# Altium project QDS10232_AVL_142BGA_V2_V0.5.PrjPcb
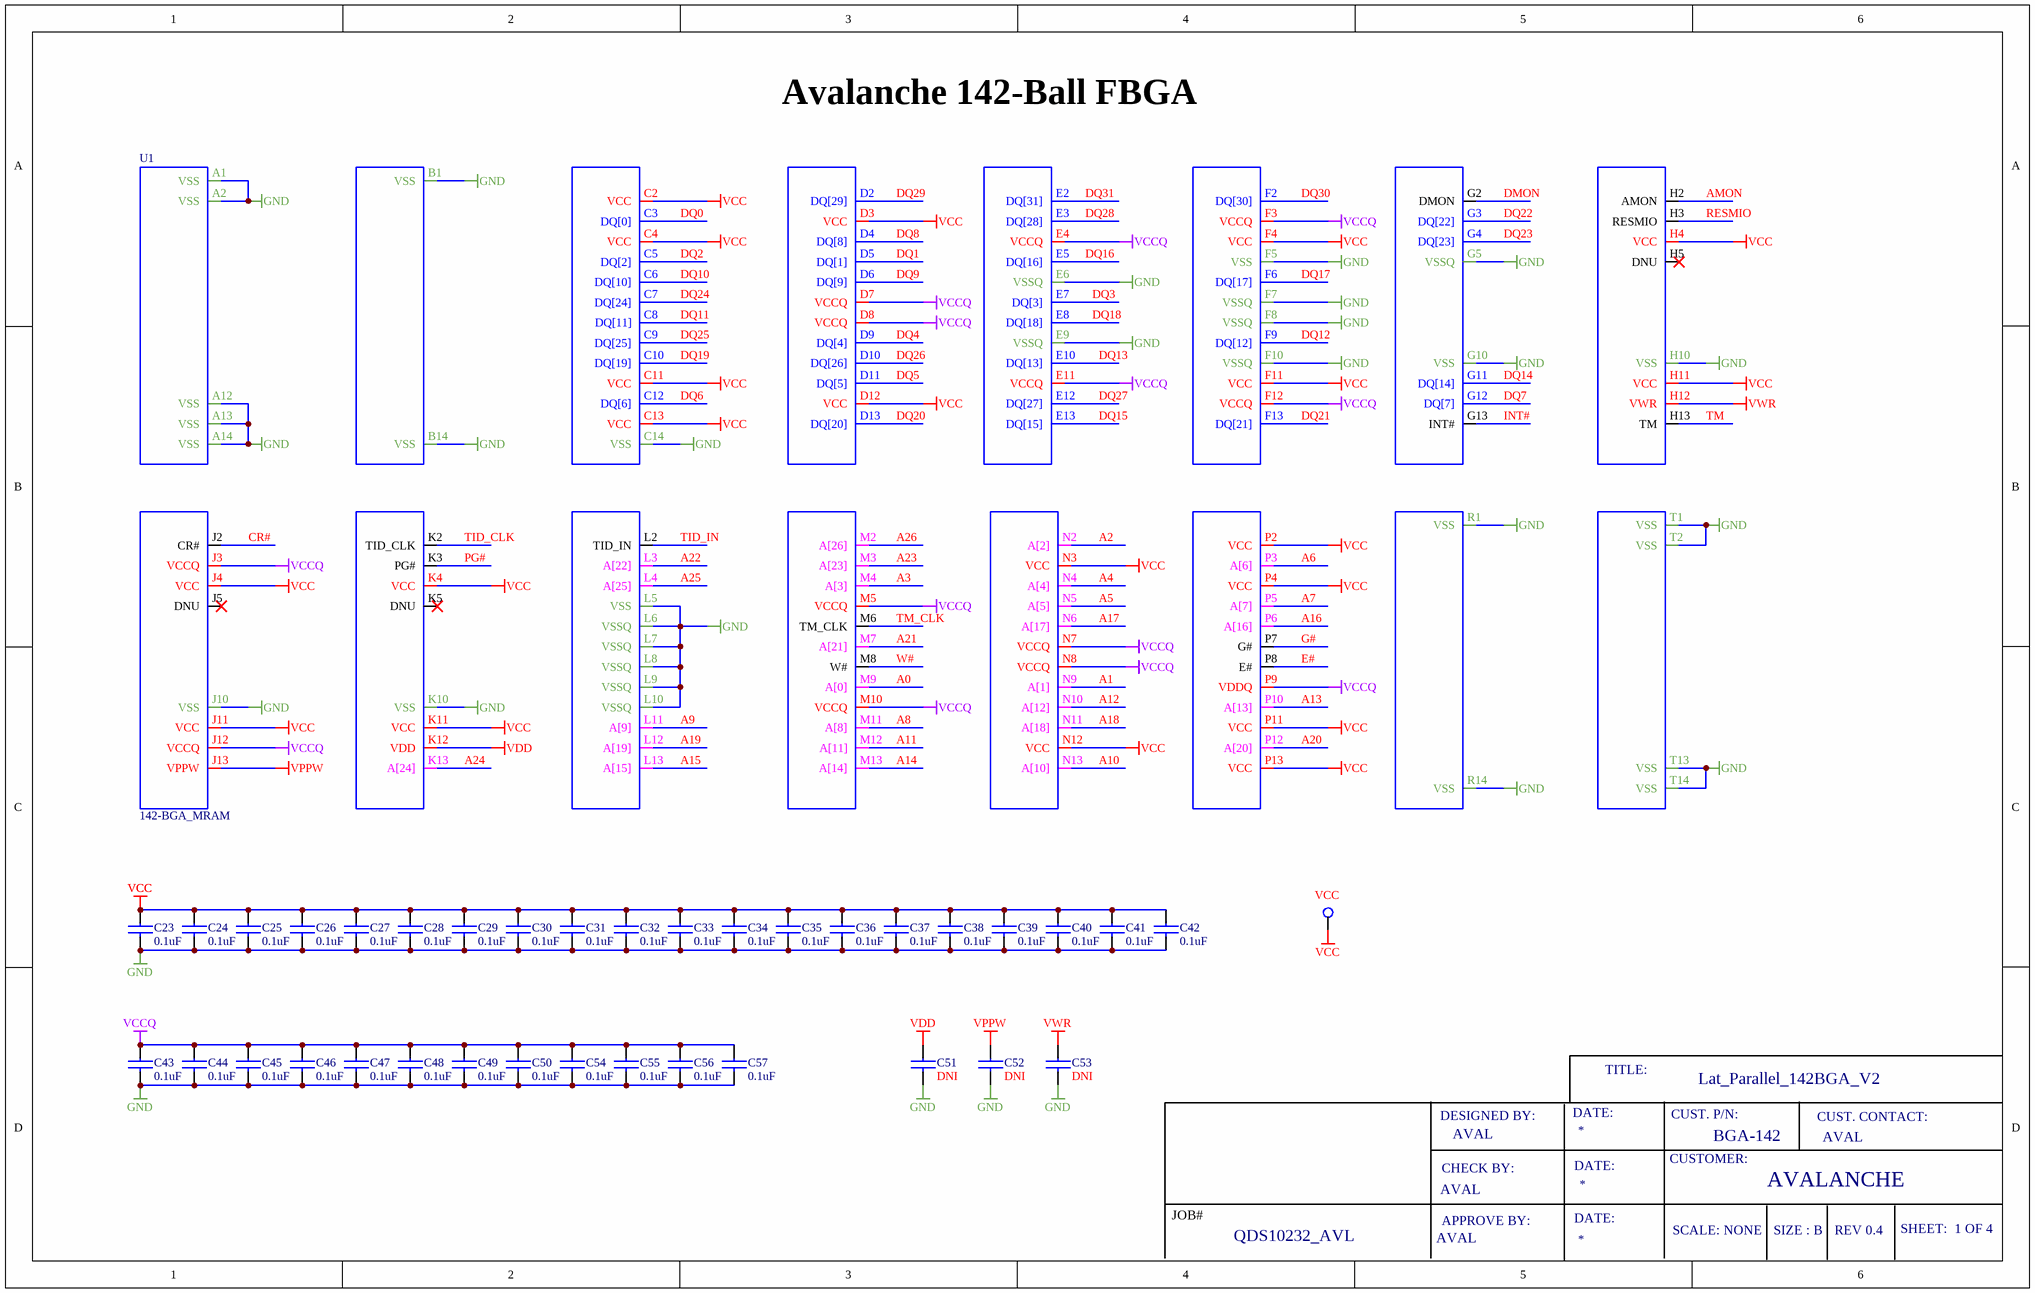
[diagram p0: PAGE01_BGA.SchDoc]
4 sheets, 249 parts. Net scope: global (net labels, ports and power ports of the same name join across sheets).
Board file: QDS10232_AVL_V0.5.PcbDoc
Sheets:
  PAGE01_BGA.SchDoc
  PAGE02_CIRCUIT.SchDoc
  PAGE03_USB_REG.SchDoc
  PAGE04_CON_J3-J4-J6-J8.SchDoc

## Sheet PAGE01_BGA.SchDoc
size B

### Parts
C23  0.1uF  [N_0402]
C24  0.1uF  [N_0402]
C25  0.1uF  [N_0402]
C26  0.1uF  [N_0402]
C27  0.1uF  [N_0402]
C28  0.1uF  [N_0402]
C29  0.1uF  [N_0402]
C30  0.1uF  [N_0402]
C31  0.1uF  [N_0402]
C32  0.1uF  [N_0402]
C33  0.1uF  [N_0402]
C34  0.1uF  [N_0402]
C35  0.1uF  [N_0402]
C36  0.1uF  [N_0402]
C37  0.1uF  [N_0402]
C38  0.1uF  [N_0402]
C39  0.1uF  [N_0402]
C40  0.1uF  [N_0402]
C41  0.1uF  [N_0402]
C42  0.1uF  [N_0402]
C43  0.1uF  [N_0402]
C44  0.1uF  [N_0402]
C45  0.1uF  [N_0402]
C46  0.1uF  [N_0402]
C47  0.1uF  [N_0402]
C48  0.1uF  [N_0402]
C49  0.1uF  [N_0402]
C50  0.1uF  [N_0402]
C51  DNI  [N_0402]
C52  DNI  [N_0402]
C53  DNI  [N_0402]
C54  0.1uF  [N_0402]
C55  0.1uF  [N_0402]
C56  0.1uF  [N_0402]
C57  0.1uF  [N_0402]
U1  142-BGA_MRAM  [BGA P1.0-142L]
VCC  TP  [TEST POINT 40X20_010819]  (value not drawn)

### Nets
A0: U1.M9(A[0])
AMON: U1.H2(AMON)
DQ0: U1.C3(DQ[0])
E#: U1.P8(E#)
G#: U1.P7(G#)
GND: C23.2 C24.2 C25.2 C26.2 C27.2 C28.2 C29.2 C30.2 C31.2 C32.2 C33.2 C34.2 C35.2 C36.2 C37.2 C38.2 C39.2 C40.2 C41.2 C42.2 C43.2 C44.2 C45.2 C46.2 C47.2 C48.2 C49.2 C50.2 C51.2 C52.2 C53.2 C54.2 C55.2 C56.2 C57.2 U1.A1(VSS) U1.A2(VSS) U1.A12(VSS) U1.A13(VSS) U1.A14(VSS) U1.B1(VSS) U1.B14(VSS) U1.C14(VSS) U1.E6(VSSQ) U1.E9(VSSQ) U1.F5(VSS) U1.F7(VSSQ) U1.F8(VSSQ) U1.F10(VSSQ) U1.G5(VSSQ) U1.G10(VSS) U1.H10(VSS) U1.J10(VSS) U1.K10(VSS) U1.L5(VSS) U1.L6(VSSQ) U1.L7(VSSQ) U1.L8(VSSQ) U1.L9(VSSQ) U1.L10(VSSQ) U1.R1(VSS) U1.R14(VSS) U1.T1(VSS) U1.T2(VSS) U1.T13(VSS) U1.T14(VSS)
RESMIO: U1.H3(RESMIO)
VCC: C23.1 C24.1 C25.1 C26.1 C27.1 C28.1 C29.1 C30.1 C31.1 C32.1 C33.1 C34.1 C35.1 C36.1 C37.1 C38.1 C39.1 C40.1 C41.1 C42.1 U1.C2(VCC) U1.C4(VCC) U1.C11(VCC) U1.C13(VCC) U1.D3(VCC) U1.D12(VCC) U1.F4(VCC) U1.F11(VCC) U1.H4(VCC) U1.H11(VCC) U1.J4(VCC) U1.J11(VCC) U1.K4(VCC) U1.K11(VCC) U1.N3(VCC) U1.N12(VCC) U1.P2(VCC) U1.P4(VCC) U1.P11(VCC) U1.P13(VCC) VCC.1(TP1)
VCCQ: C43.1 C44.1 C45.1 C46.1 C47.1 C48.1 C49.1 C50.1 C54.1 C55.1 C56.1 C57.1 U1.D7(VCCQ) U1.D8(VCCQ) U1.E4(VCCQ) U1.E11(VCCQ) U1.F3(VCCQ) U1.F12(VCCQ) U1.J3(VCCQ) U1.J12(VCCQ) U1.M5(VCCQ) U1.M10(VCCQ) U1.N7(VCCQ) U1.N8(VCCQ) U1.P9(VDDQ)
VDD: C51.1 U1.K12(VDD)
VPPW: C52.1 U1.J13(VPPW)
VWR: C53.1 U1.H12(VWR)
W#: U1.M8(W#)
A1: U1.N9(A[1])
A2: U1.N2(A[2])
A3: U1.M4(A[3])
A4: U1.N4(A[4])
A5: U1.N5(A[5])
A6: U1.P3(A[6])
A7: U1.P5(A[7])
A8: U1.M11(A[8])
A9: U1.L11(A[9])
A10: U1.N13(A[10])
A11: U1.M12(A[11])
A12: U1.N10(A[12])
A13: U1.P10(A[13])
A14: U1.M13(A[14])
A15: U1.L13(A[15])
A16: U1.P6(A[16])
A17: U1.N6(A[17])
A18: U1.N11(A[18])
A19: U1.L12(A[19])
A20: U1.P12(A[20])
A21: U1.M7(A[21])
A22: U1.L3(A[22])
A23: U1.M3(A[23])
A24: U1.K13(A[24])
A25: U1.L4(A[25])
A26: U1.M2(A[26])
CR#: U1.J2(CR#)
DMON: U1.G2(DMON)
DQ1: U1.D5(DQ[1])
DQ2: U1.C5(DQ[2])
DQ3: U1.E7(DQ[3])
DQ4: U1.D9(DQ[4])
DQ5: U1.D11(DQ[5])
DQ6: U1.C12(DQ[6])
DQ7: U1.G12(DQ[7])
DQ8: U1.D4(DQ[8])
DQ9: U1.D6(DQ[9])
DQ10: U1.C6(DQ[10])
DQ11: U1.C8(DQ[11])
DQ12: U1.F9(DQ[12])
DQ13: U1.E10(DQ[13])
DQ14: U1.G11(DQ[14])
DQ15: U1.E13(DQ[15])
DQ16: U1.E5(DQ[16])
DQ17: U1.F6(DQ[17])
DQ18: U1.E8(DQ[18])
DQ19: U1.C10(DQ[19])
DQ20: U1.D13(DQ[20])
DQ21: U1.F13(DQ[21])
DQ22: U1.G3(DQ[22])
DQ23: U1.G4(DQ[23])
DQ24: U1.C7(DQ[24])
DQ25: U1.C9(DQ[25])
DQ26: U1.D10(DQ[26])
DQ27: U1.E12(DQ[27])
DQ28: U1.E3(DQ[28])
DQ29: U1.D2(DQ[29])
DQ30: U1.F2(DQ[30])
DQ31: U1.E2(DQ[31])
INT#: U1.G13(INT#)
PG#: U1.K3(PG#)
TID_CLK: U1.K2(TID_CLK)
TID_IN: U1.L2(TID_IN)
TM: U1.H13(TM)
TM_CLK: U1.M6(TM_CLK)

Not connected (* = marked no-connect by the designer): U1 H5(DNU)* J5(DNU)* K5(DNU)*

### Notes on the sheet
- Avalanche 142-Ball FBGA
- TITLE:
- Lat_Parallel_142BGA_V2
- DESIGNED BY:
- CHECK BY:
- AVAL
- DATE:
- CUSTOMER:
- CUST. P/N:
- BGA-142
- CUST. CONTACT:
- JOB#
- QDS10232_AVL
- APPROVE BY:
- SCALE: NONE
- AVALANCHE
- SIZE : B
- REV 0.4
- SHEET:  1 OF 4

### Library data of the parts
C23-C50 = CAP: CAP CER 10000PF 50V X7R 0402; Part Number: GCM188R71C104KA37D
C51-C53 = CAP
C54-C57 = CAP: Part Number: GCM188R71C104KA37D
VCC = TEST POINT 1: VALUE: COPPER FEATURE

## Sheet PAGE02_CIRCUIT.SchDoc
size 419 x 266 mm
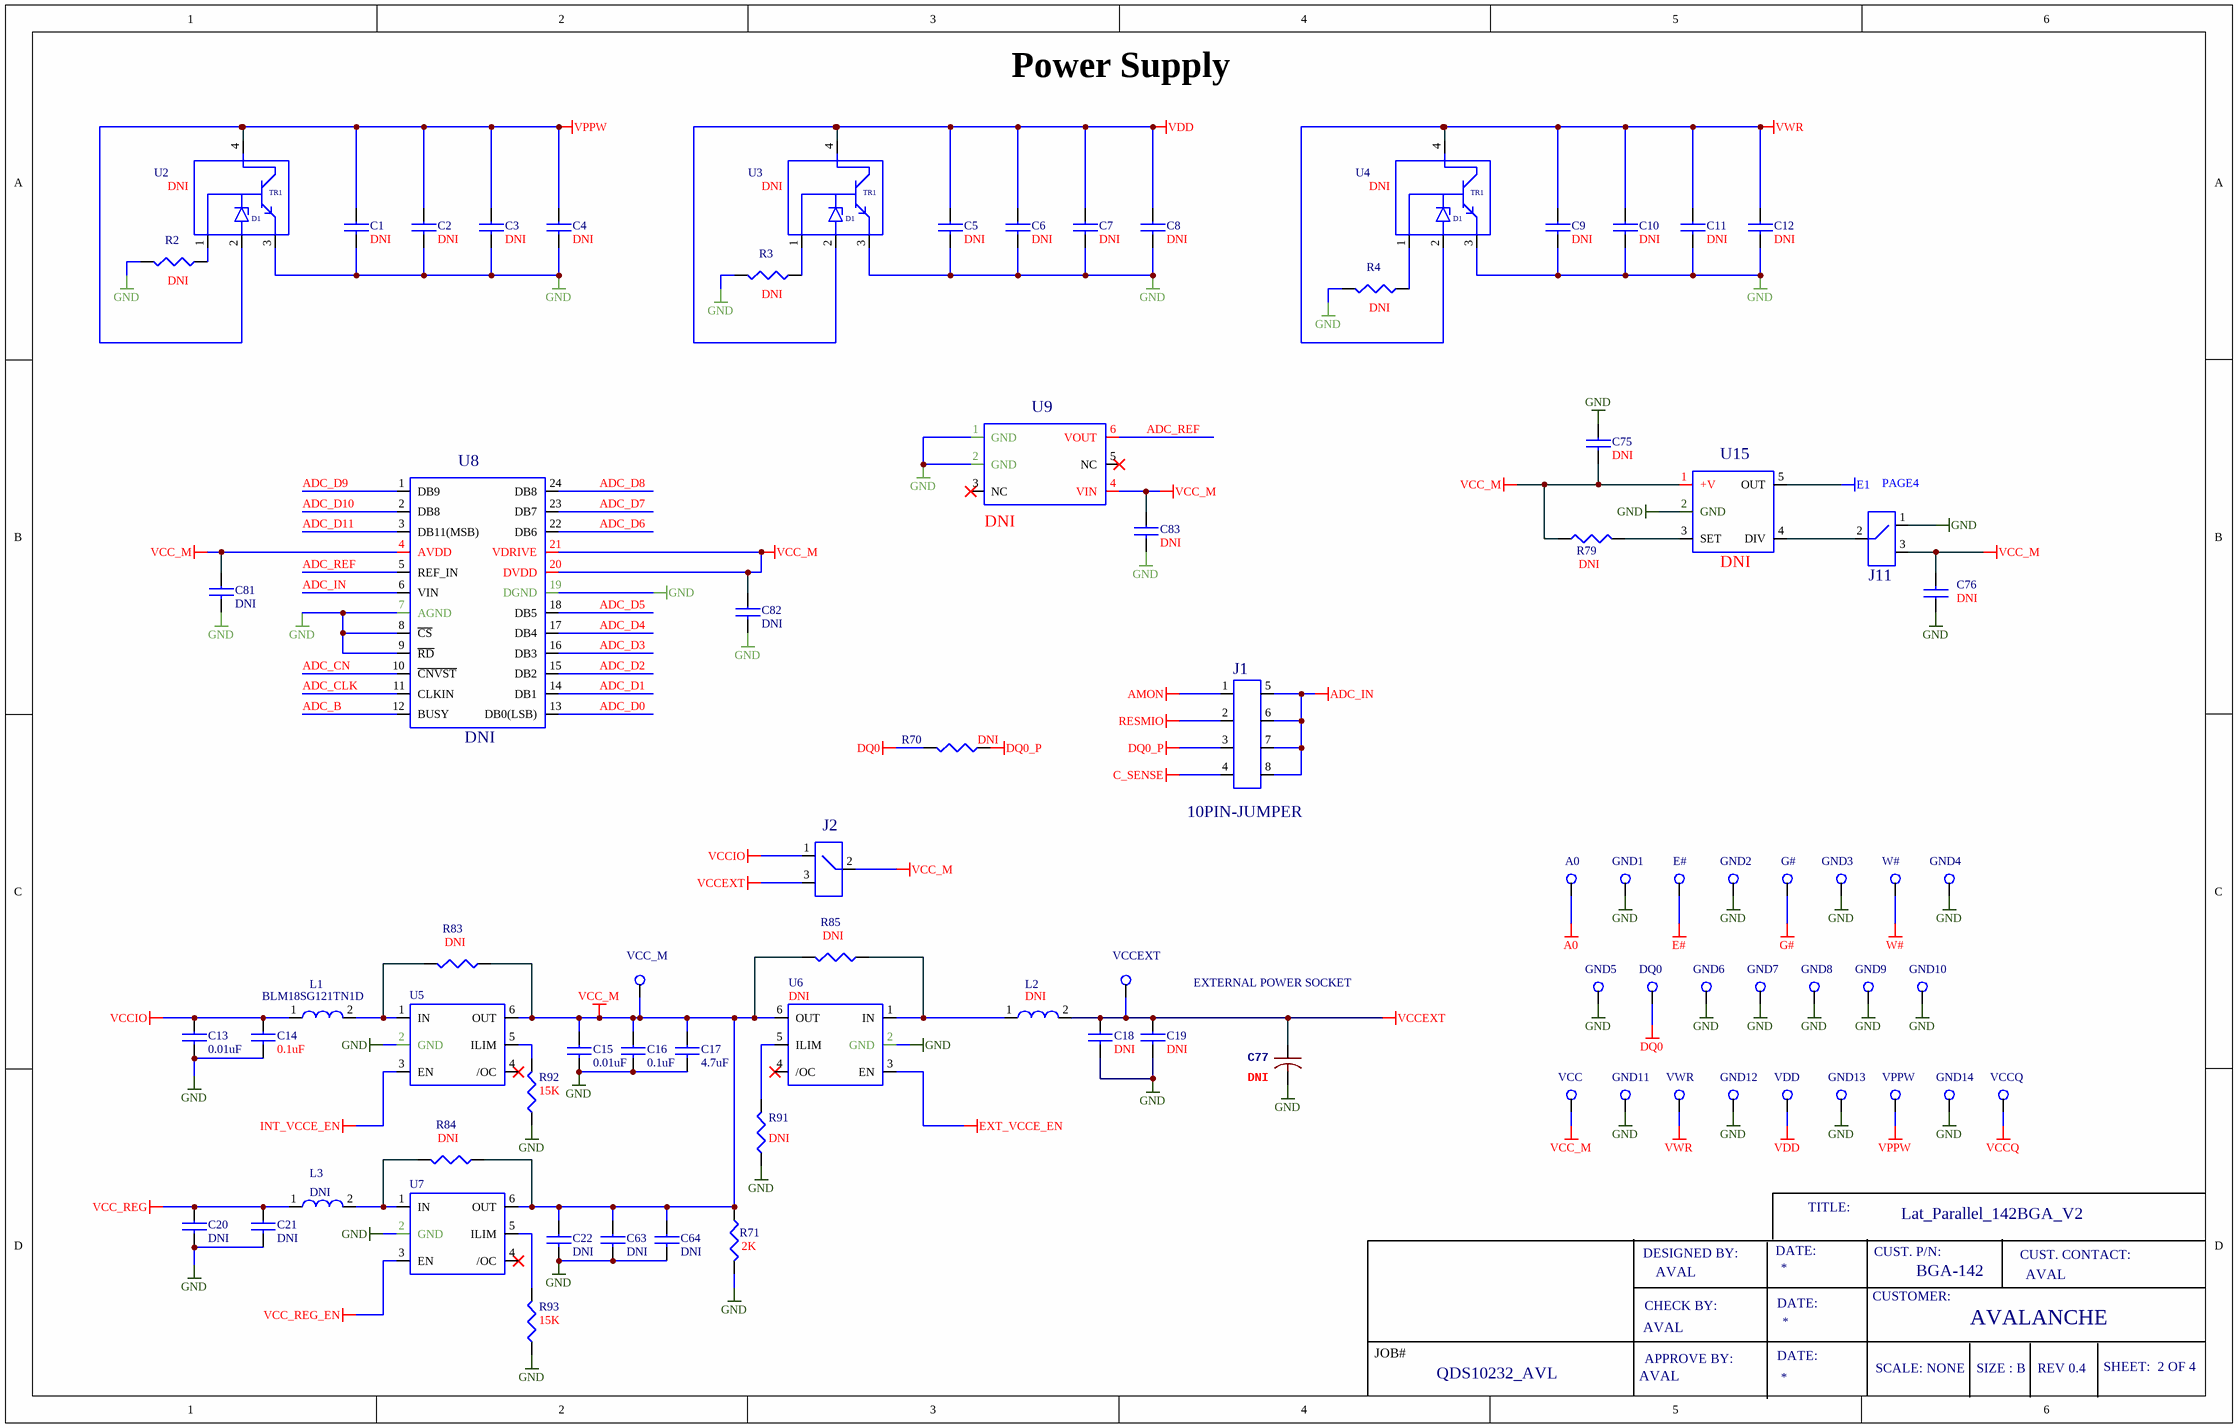
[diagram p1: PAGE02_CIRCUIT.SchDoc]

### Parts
A0  (no value)  [TEST POINT]
C1  DNI  [N_0603]
C2  DNI  [N_0603]
C3  DNI  [N_0603]
C4  DNI  [N_0603]
C5  DNI  [N_0603]
C6  DNI  [N_0603]
C7  DNI  [N_0603]
C8  DNI  [N_0603]
C9  DNI  [N_0603]
C10  DNI  [N_0603]
C11  DNI  [N_0603]
C12  DNI  [N_0603]
C13  0.01uF  [N_0603]
C14  0.1uF  [N_0603]
C15  0.01uF  [N_0603]
C16  0.1uF  [N_0603]
C17  4.7uF  [N_0603]
C18  DNI  [N_0603]
C19  DNI  [N_0603]
C20  DNI  [N_0603]
C21  DNI  [N_0603]
C22  DNI  [N_0603]
C63  DNI  [N_0603]
C64  DNI  [N_0603]
C75  DNI  [N_0402]
C76  DNI  [N_0402]
C77  DNI  [N_1206]
C81  DNI  [N_0402]
C82  DNI  [N_0402]
C83  DNI  [N_0402]
DQ0  (no value)  [TEST POINT]
E#  (no value)  [TEST POINT]
G#  (no value)  [TEST POINT]
GND1  GND  [TEST POINT]  (value not drawn)
GND2  GND  [TEST POINT]  (value not drawn)
GND3  GND  [TEST POINT]  (value not drawn)
GND4  GND  [TEST POINT]  (value not drawn)
GND5  GND  [TEST POINT]  (value not drawn)
GND6  GND  [TEST POINT]  (value not drawn)
GND7  GND  [TEST POINT]  (value not drawn)
GND8  GND  [TEST POINT]  (value not drawn)
GND9  GND  [TEST POINT]  (value not drawn)
GND10  GND  [TEST POINT 40X20_010819]  (value not drawn)
GND11  GND  [TEST POINT]  (value not drawn)
GND12  GND  [TEST POINT]  (value not drawn)
GND13  GND  [TEST POINT]  (value not drawn)
GND14  GND  [TEST POINT]  (value not drawn)
J1  10PIN-JUMPER  [1X5_HDR]
J2  3PIN-JUMPER  [JUMPER_3PIN]  (value not drawn)
J11  3PIN-JUMPER  [JUMPER_3PIN]  (value not drawn)
L1  BLM18SG121TN1D  [N_0603]
L2  DNI  [N_0603]
L3  DNI  [N_0603]
R2  DNI  [N_0603]
R3  DNI  [N_0603]
R4  DNI  [N_0603]
R70  DNI  [N_0402]
R71  2K  [N_0603]
R79  DNI  [N_0402]
R83  DNI  [N_0402]
R84  DNI  [N_0402]
R85  DNI  [N_0402]
R91  DNI  [N_0402]
R92  15K  [N_0402]
R93  15K  [N_0402]
U2  DNI  [SOT223-PVR100AZ-B]
U3  DNI  [SOT223-PVR100AZ-B]
U4  DNI  [SOT223-PVR100AZ-B]
U5  (no value)  [SSOP6A]
U6  value DNI  [SSOP6A]
U7  (no value)  [SSOP6A]
U8  DNI  [TSSOP24]
U9  DNI  [SOT23]
U15  DNI  [TSOP_23]
VCC1  VCC  [TEST POINT]
VCC_M  TP  [TEST POINT 40X20_010819]  (value not drawn)
VCCEXT  TP  [TEST POINT 40X20_010819]  (value not drawn)
VCCQ  (no value)  [TEST POINT]
VDD  VDD  [TEST POINT]  (value not drawn)
VPPW  (no value)  [TEST POINT]
VWR  (no value)  [TEST POINT]
W#  (no value)  [TEST POINT]

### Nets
A0: A0.1(TP1)
ADC_IN: J1.5 J1.6 J1.7 J1.8 U8.6(VIN)
AMON: J1.1
C_SENSE: J1.4
DQ0: DQ0.1(TP1) R70.2
DQ0_P: J1.3 R70.1
E1: U15.5(OUT)
E#: E#.1(TP1)
EXT_VCCE_EN: U6.3(EN)
G#: G#.1(TP1)
GND: C1.2 C2.2 C3.2 C4.2 C5.2 C6.2 C7.2 C8.2 C9.2 C10.2 C11.2 C12.2 C13.2 C14.2 C15.2 C16.2 C17.2 C18.2 C19.2 C20.2 C21.2 C22.2 C63.2 C64.2 C75.1 C76.1 C77.2 C81.2 C82.2 C83.2 GND1.1(TP1) GND2.1(TP1) GND3.1(TP1) GND4.1(TP1) GND5.1(TP1) GND6.1(TP1) GND7.1(TP1) GND8.1(TP1) GND9.1(TP1) GND10.1(TP1) GND11.1(TP1) GND12.1(TP1) GND13.1(TP1) GND14.1(TP1) J11.1 R2.2 R3.2 R4.2 R71.2 R91.2 R92.2 R93.2 U2.3 U3.3 U4.3 U5.2(GND) U6.2(GND) U7.2(GND) U8.7(AGND) U8.8(~{CS}) U8.9(~{RD}) U8.19(DGND) U9.1(GND) U9.2(GND) U15.2(GND)
INT_VCCE_EN: U5.3(EN)
RESMIO: J1.2
VCC_M: C15.1 C16.1 C17.1 C22.1 C63.1 C64.1 C75.2 C76.2 C81.1 C82.1 C83.1 J2.2 J11.3 R71.1 R79.1 R83.1 R84.1 R85.2 U5.6(OUT) U6.6(OUT) U7.6(OUT) U8.4(AVDD) U8.20(DVDD) U8.21(VDRIVE) U9.4(VIN) U15.1(+V) VCC1.1(TP1) VCC_M.1(TP1)
VCC_REG: C20.1 C21.1 L3.1
VCC_REG_EN: U7.3(EN)
VCCEXT: C18.1 C19.1 C77.1 J2.3 L2.2 VCCEXT.1(TP1)
VCCIO: C13.1 C14.1 J2.1 L1.1
VCCQ: VCCQ.1(TP1)
VDD: C5.1 C6.1 C7.1 C8.1 U3.2 U3.4 VDD.1(TP1)
VPPW: C1.1 C2.1 C3.1 C4.1 U2.2 U2.4 VPPW.1(TP1)
VWR: C9.1 C10.1 C11.1 C12.1 U4.2 U4.4 VWR.1(TP1)
W#: W#.1(TP1)
ADC_B: U8.12(BUSY)
ADC_CLK: U8.11(CLKIN)
ADC_CN: U8.10(~{CNVST})
ADC_D0: U8.13(DB0(LSB))
ADC_D1: U8.14(DB1)
ADC_D2: U8.15(DB2)
ADC_D3: U8.16(DB3)
ADC_D4: U8.17(DB4)
ADC_D5: U8.18(DB5)
ADC_D6: U8.22(DB6)
ADC_D7: U8.23(DB7)
ADC_D8: U8.24(DB8)
ADC_D9: U8.1(DB9)
ADC_D10: U8.2(DB8)
ADC_D11: U8.3(DB11(MSB))
ADC_REF: U8.5(REF_IN) U9.6(VOUT)
NetJ11_2: J11.2 U15.4(DIV)
NetL1_2: L1.2 R83.2 U5.1(IN)
NetL2_1: L2.1 R85.1 U6.1(IN)
NetL3_2: L3.2 R84.2 U7.1(IN)
NetR2_1: R2.1 U2.1
NetR3_1: R3.1 U3.1
NetR4_1: R4.1 U4.1
NetR79_2: R79.2 U15.3(SET)
NetR91_1: R91.1 U6.5(ILIM)
NetR92_1: R92.1 U5.5(ILIM)
NetR93_1: R93.1 U7.5(ILIM)

Not connected (* = marked no-connect by the designer): U5 4(/OC)*; U6 4(/OC)*; U7 4(/OC)*; U9 3(NC)* 5(NC)*

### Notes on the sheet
- Power Supply
- (near J11) PAGE4
- EXTERNAL POWER SOCKET
- TITLE:
- Lat_Parallel_142BGA_V2
- DESIGNED BY:
- CHECK BY:
- AVAL
- DATE:
- CUSTOMER:
- CUST. P/N:
- BGA-142
- CUST. CONTACT:
- JOB#
- QDS10232_AVL
- APPROVE BY:
- SCALE: NONE
- AVALANCHE
- SIZE : B
- REV 0.4
- SHEET:  2 OF 4

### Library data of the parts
A0 DQ0 E# G# GND1-GND14 VCC1 VCC_M VCCEXT VCCQ VDD VPPW VWR W# = TEST POINT 1: VALUE: COPPER FEATURE
C1-C12 C18-C22 C63 C64 C75 C76 C81-C83 = CAP
C13 C15 = CAP: CAP CER 10000PF 50V X7R 0603; Part Number: CC0603KPX7R9BB103
C14 C16 = CAP: CAP CER 0.1UF 16V X7R 0603; Part Number: GCM188R71C104KA37D
C17 = CAP: CAP CER 4.7UF 6.3V X7R 0603; Part Number: CL10B475KQ8NQNC
C77 = C-USC0603
J1 = 5PIN-JUMPER
L1 = FB: FERRITE BEAD 120 OHM 0603 1LN; Value: 120 OHM
L2 L3 = FB
R2-R4 R70 R79 R83-R85 = RES
R71 = RES: RES SMD 2K OHM 1% 1/10W 0603; Part Number: ERJ-U03F2001V
R91 = RES: RES 2K OHM 1% 1/10W 0603 SMD; Part Number: TNPW040215K0BEED; Manufacturer: Vishay Dale; Value: 15K
R92 R93 = RES: RES 2K OHM 1% 1/10W 0603 SMD; Part Number: TNPW040215K0BEED; Manufacturer: Vishay Dale
U2-U4 = PVR100AZ-B: PVR100AZ-B3V3,115
U5-U7 = BD2244G-M
U8 = AD7472: IC ADC 12BIT SAR 24TSSOP; Part Number: AD7472BRUZ-REEL7
U9 = LT6654AHS6-2.5: IC VREF SERIES 0.05% TSOT23-6; Part Number: LT6654AHS6-2.5#TRPBF
U15 = LTC6905: IC OSC SILICON PROG TSOT23-5; Part Number: LTC6905IS5#TRMPBF

## Sheet PAGE03_USB_REG.SchDoc
size B
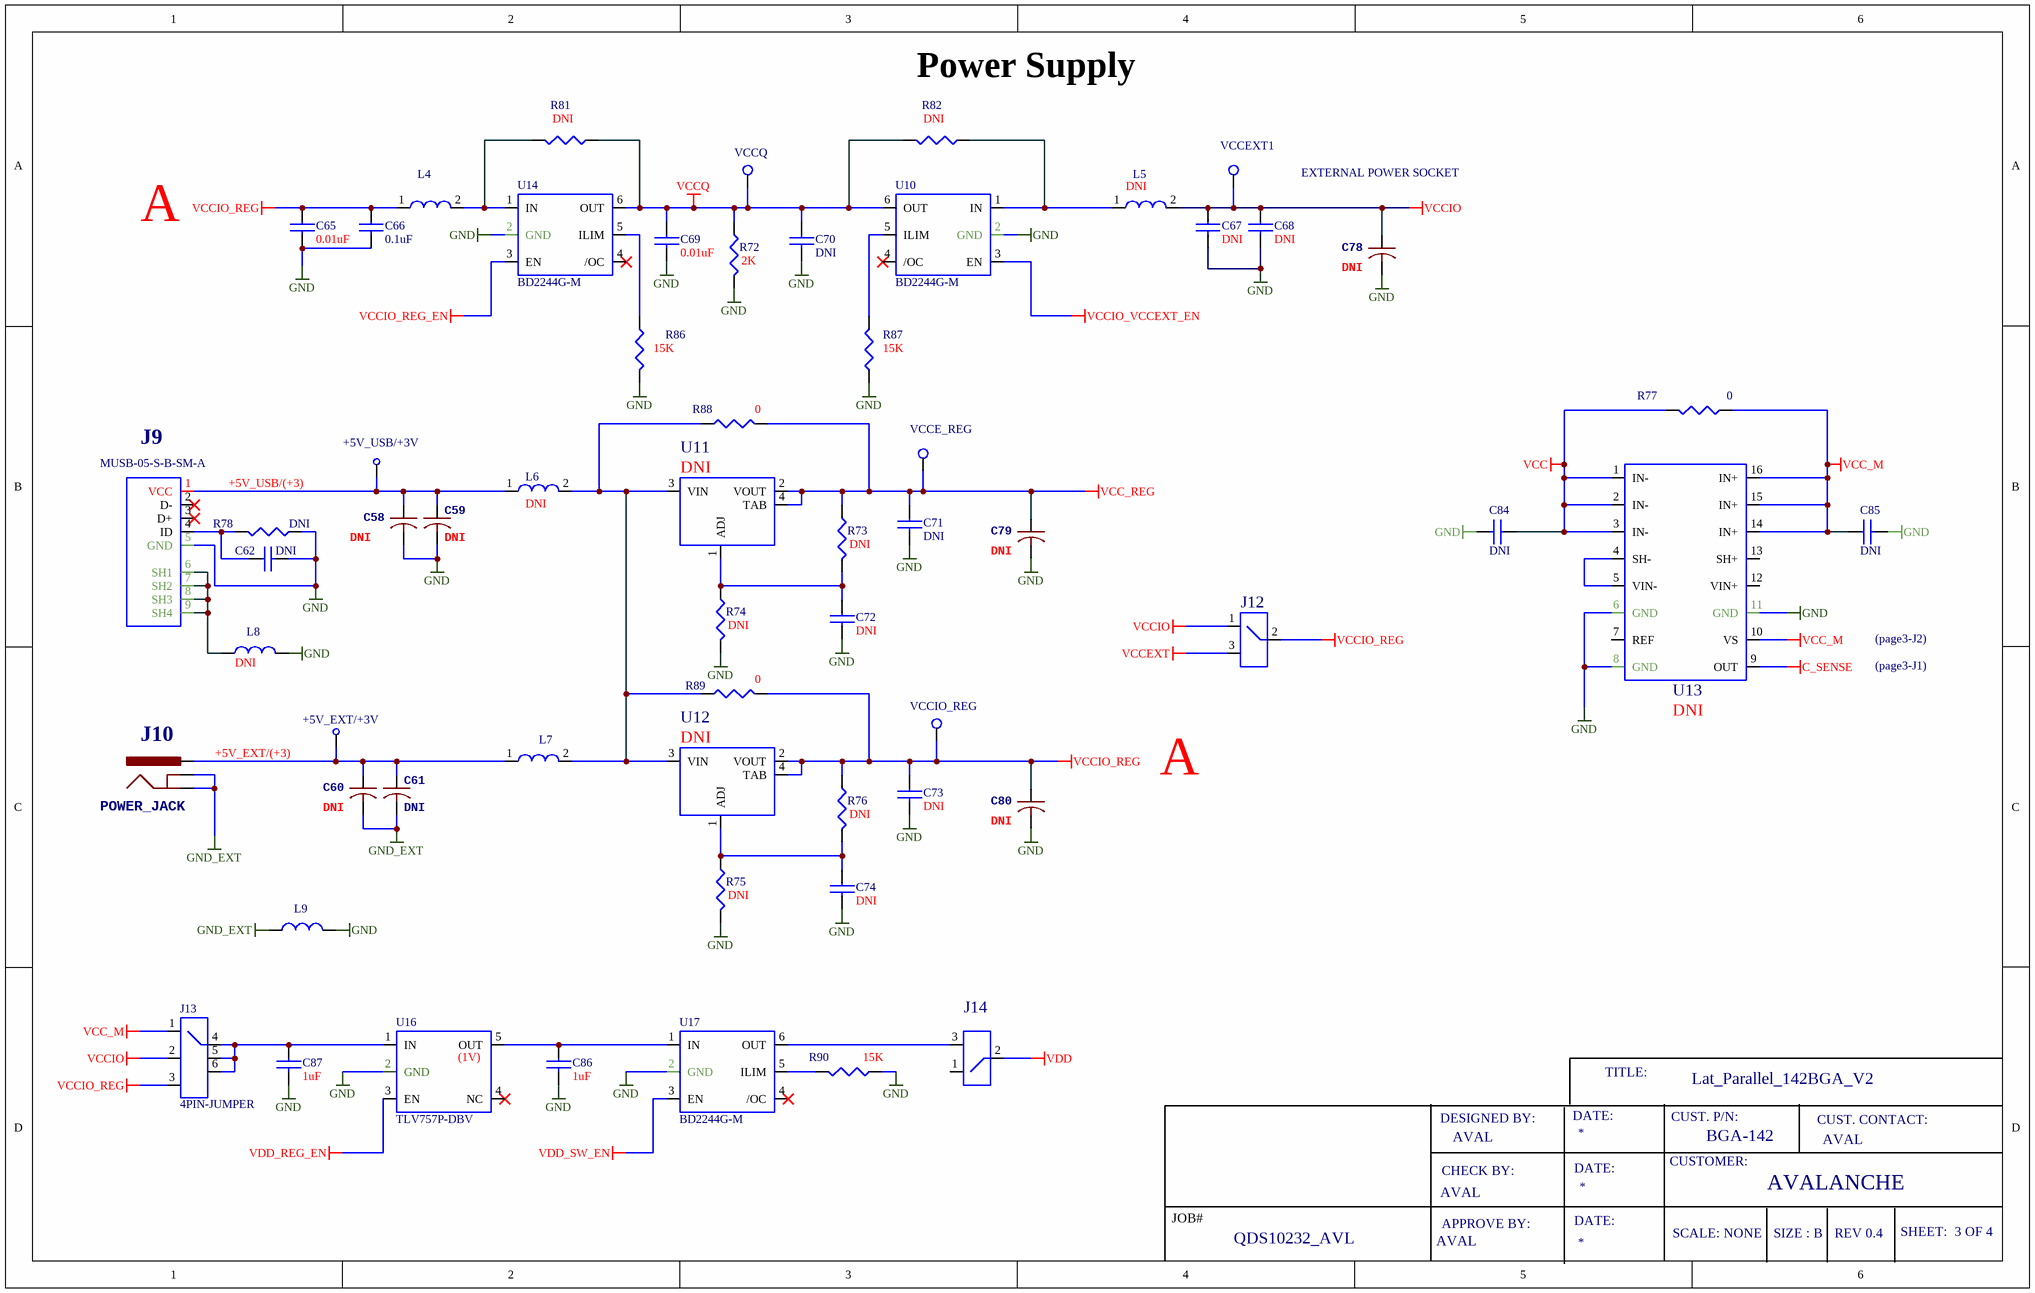
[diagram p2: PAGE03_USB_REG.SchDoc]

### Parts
+5V_EXT/+3V  TESTPOINT  [TEST POINT]  (value not drawn)
+5V_USB/+3V  TESTPOINT  [TEST POINT]  (value not drawn)
C58  DNI  [N_1206]
C59  DNI  [N_0603]
C60  DNI  [N_1206]
C61  DNI  [N_0603]
C62  DNI  [N_0603]
C65  0.01uF  [N_0603]
C66  0.1uF  [N_0603]
C67  DNI  [N_0603]
C68  DNI  [N_0603]
C69  0.01uF  [N_0603]
C70  DNI  [N_0603]
C71  DNI  [N_0603]
C72  DNI  [N_0805]
C73  DNI  [N_0603]
C74  DNI  [N_0805]
C78  DNI  [N_1206]
C79  DNI  [N_1206]
C80  DNI  [N_1206]
C84  DNI  [N_0402]
C85  DNI  [N_0402]
C86  1uF  [N_0603]
C87  1uF  [N_0603]
J9  MUSB-05-S-B-SM-A  [MUSB-05-S-B-SM-A]
J10  POWER_JACK  [POWER_JACK_PTH]
J12  3PIN-JUMPER  [JUMPER_3PIN]  (value not drawn)
J13  4PIN-JUMPER  [1X4_HDR]
J14  3PIN-JUMPER  [JUMPER_3PIN]  (value not drawn)
L4  (no value)  [N_0603]
L5  DNI  [N_0603]
L6  DNI  [N_0603]
L7  (no value)  [N_0603]
L8  DNI  [FB_2743019447]
L9  (no value)
R72  2K  [N_0402]
R73  DNI  [N_0603]
R74  DNI  [N_0603]
R75  DNI  [N_0603]
R76  DNI  [N_0603]
R77  0  [N_0402]
R78  DNI  [N_0603]
R81  DNI  [N_0402]
R82  DNI  [N_0402]
R86  15K  [N_0402]
R87  15K  [N_0402]
R88  0  [N_0603]
R89  0  [N_0603]
R90  15K  [N_0402]
U10  BD2244G-M  [SSOP6A]
U11  DNI  [SOT223-PVR100AZ-B]
U12  DNI  [SOT223-PVR100AZ-B]
U13  DNI  [PW16]
U14  BD2244G-M  [SSOP6A]
U16  TLV757P-DBV  [SOT23-5]
U17  BD2244G-M  [SSOP6A]
VCCE_REG  TP  [TEST POINT 40X20_010819]  (value not drawn)
VCCEXT1  TP  [TEST POINT 40X20_010819]  (value not drawn)
VCCIO_REG  TP  [TEST POINT]  (value not drawn)
VCCQ1  VCCQ  [TEST POINT 40X20_010819]

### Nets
C_SENSE: U13.9(OUT)
GND: C58.2 C59.2 C62.2 C65.2 C66.2 C67.2 C68.2 C69.2 C70.2 C71.2 C72.2 C73.2 C74.2 C78.2 C79.2 C80.2 C84.2 C85.2 C86.2 C87.2 J9.5(GND) L8.1 L9.1 R72.2 R74.2 R75.2 R78.1 R86.2 R87.2 R90.2 U10.2(GND) U13.6(GND) U13.8(GND) U13.11(GND) U14.2(GND) U16.2(GND) U17.2(GND)
GND_EXT: C60.2 C61.2 J10.GND J10.GNDBREAK L9.2
VCC: C84.1 R77.2 U13.1(IN-) U13.2(IN-) U13.3(IN-)
VCC_M: C85.1 J13.1 R77.1 U13.10(VS) U13.14(IN+) U13.15(IN+) U13.16(IN+)
VCC_REG: C71.1 C79.1 R73.1 R88.2 U11.2(VOUT) U11.4(TAB) VCCE_REG.1(TP1)
VCCEXT: J12.3
VCCIO: C67.1 C68.1 C78.1 J12.1 J13.2 L5.2 VCCEXT1.1(TP1)
VCCIO_REG: C65.1 C66.1 C73.1 C80.1 J12.2 J13.3 L4.1 R76.1 R89.2 U12.2(VOUT) U12.4(TAB) VCCIO_REG.1(TP1)
VCCIO_REG_EN: U14.3(EN)
VCCIO_VCCEXT_EN: U10.3(EN)
VCCQ: C69.1 C70.1 R72.1 R81.1 R82.2 U10.6(OUT) U14.6(OUT) VCCQ1.1(TP1)
VDD: J14.2
VDD_REG_EN: U16.3(EN)
VDD_SW_EN: U17.3(EN)
+5V_EXT/(+3): +5V_EXT/+3V.1(TP1) C60.1 C61.1 J10.PWR L7.1
+5V_USB/(+3): +5V_USB/+3V.1(TP1) C58.1 C59.1 J9.1(VCC) L6.1
NetC62_1: C62.1 J9.4(ID) R78.2
NetC72_1: C72.1 R73.2 R74.1 U11.1(ADJ)
NetC74_1: C74.1 R75.1 R76.2 U12.1(ADJ)
NetC86_1: C86.1 U16.5(OUT) U17.1(IN)
NetC87_1: C87.1 J13.4 J13.5 J13.6 U16.1(IN)
NetJ9_6: J9.6(SH1) J9.7(SH2) J9.8(SH3) J9.9(SH4) L8.2
NetJ14_3: J14.3 U17.6(OUT)
NetL4_2: L4.2 R81.2 U14.1(IN)
NetL5_1: L5.1 R82.1 U10.1(IN)
NetL6_2: L6.2 L7.2 R88.1 R89.1 U11.3(VIN) U12.3(VIN)
NetR86_1: R86.1 U14.5(ILIM)
NetR87_1: R87.1 U10.5(ILIM)
NetR90_1: R90.1 U17.5(ILIM)
NetU13_4: U13.4(SH-) U13.5(VIN-)

Not connected (* = marked no-connect by the designer): J9 2(D-)* 3(D+)*; J14 1; U10 4(/OC)*; U13 7(REF) 12(VIN+) 13(SH+); U14 4(/OC)*; U16 4(NC)*; U17 4(/OC)*

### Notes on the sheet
- Power Supply
- A
- EXTERNAL POWER SOCKET
- (page3-J2)
- (page3-J1)
- TITLE:
- Lat_Parallel_142BGA_V2
- DESIGNED BY:
- CHECK BY:
- AVAL
- DATE:
- CUSTOMER:
- CUST. P/N:
- BGA-142
- CUST. CONTACT:
- JOB#
- QDS10232_AVL
- APPROVE BY:
- SCALE: NONE
- AVALANCHE
- SIZE : B
- REV 0.4
- SHEET:  3 OF 4

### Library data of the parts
+5V_EXT/+3V +5V_USB/+3V VCCE_REG VCCEXT1 VCCIO_REG VCCQ1 = TEST POINT 1: VALUE: COPPER FEATURE
C58-C61 C78-C80 = C-USC0603
C62 C67 C68 C70-C74 C84 C85 = CAP
C65 C69 = CAP: as C13 on sheet PAGE02_CIRCUIT
C66 = CAP: as C14 on sheet PAGE02_CIRCUIT
C86 C87 = CAP: DNI; Part Number: CL10A105KB8NNNC
J9 = MUSB-05-S-B-SM-A: Part Number: 5075BMR-05-SM-CR
L4 = FB: Part Number: BLM18SG121TN1D
L5 L6 = FB
L7 = FB: DNI, SHORT IT ACROSS
L8 L9 = INDUCTOR
R72 = RES: RES 2K OHM 1% 1/10W 0603 SMD; Part Number: ERJ-U03F2001V
R73-R76 R78 R81 R82 R88 R89 = RES
R77 = RES: Part Number: RC0402JR-070RL
R86 R87 R90 = RES: as R92 on sheet PAGE02_CIRCUIT
U10 U14 U17 = BD2244G-M: MANUFACTURER: ROHM
U11 U12 = LD1117STR: "Remove U11, U12, Short (connect) pins 1,2,3 for U11, and U12"
U13 = INA250A4_TSSOP16: IC CURR SENSE 1 CIRCUIT 16TSSOP; Part Number: INA250A4PWR

## Sheet PAGE04_CON_J3-J4-J6-J8.SchDoc
size 444 x 304 mm
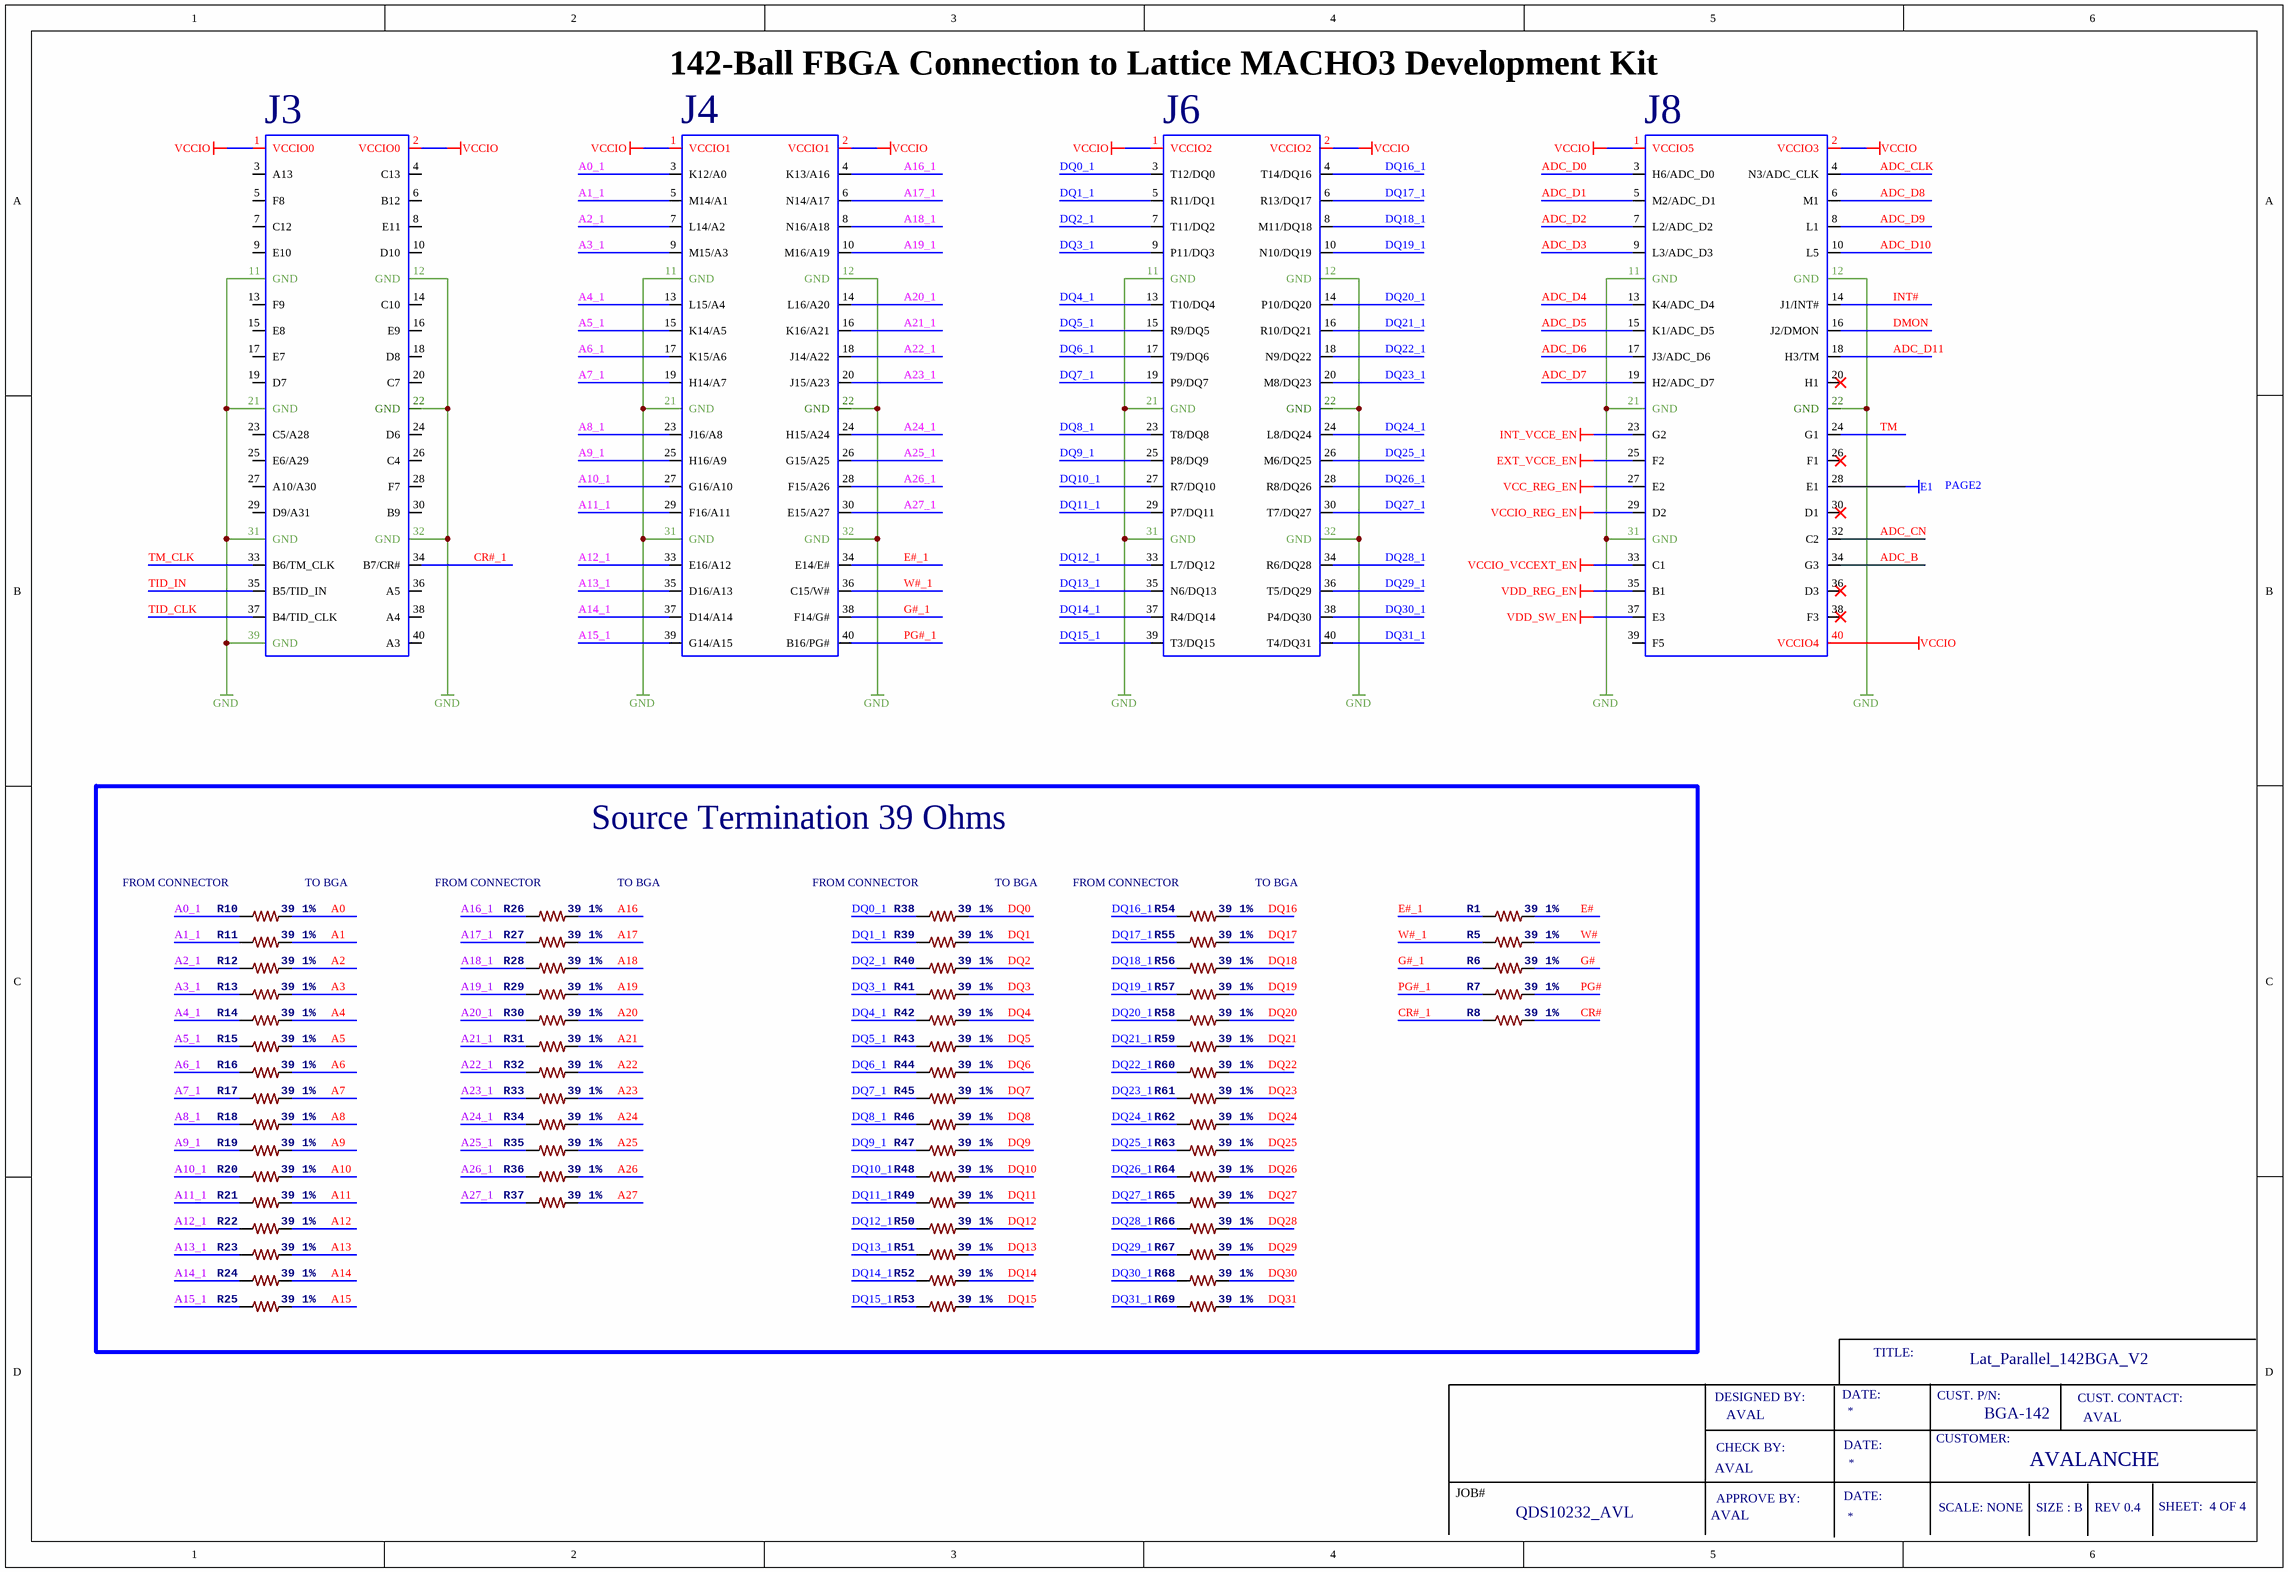
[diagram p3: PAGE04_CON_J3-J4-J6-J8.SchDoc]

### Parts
J3  J3_2X10  [2X10-HEADER]  (value not drawn)
J4  J4_2X10  [2X10-HEADER]  (value not drawn)
J6  J6_2X10  [2X10-HEADER]  (value not drawn)
J8  J8_2X10  [2X10-HEADER]  (value not drawn)
R1  39 1%  [N_0402]
R5  39 1%  [N_0402]
R6  39 1%  [N_0402]
R7  39 1%  [N_0402]
R8  39 1%  [N_0402]
R10  39 1%  [N_0402]
R11  39 1%  [N_0402]
R12  39 1%  [N_0402]
R13  39 1%  [N_0402]
R14  39 1%  [N_0402]
R15  39 1%  [N_0402]
R16  39 1%  [N_0402]
R17  39 1%  [N_0402]
R18  39 1%  [N_0402]
R19  39 1%  [N_0402]
R20  39 1%  [N_0402]
R21  39 1%  [N_0402]
R22  39 1%  [N_0402]
R23  39 1%  [N_0402]
R24  39 1%  [N_0402]
R25  39 1%  [N_0402]
R26  39 1%  [N_0402]
R27  39 1%  [N_0402]
R28  39 1%  [N_0402]
R29  39 1%  [N_0402]
R30  39 1%  [N_0402]
R31  39 1%  [N_0402]
R32  39 1%  [N_0402]
R33  39 1%  [N_0402]
R34  39 1%  [N_0402]
R35  39 1%  [N_0402]
R36  39 1%  [N_0402]
R37  39 1%  [N_0402]
R38  39 1%  [N_0402]
R39  39 1%  [N_0402]
R40  39 1%  [N_0402]
R41  39 1%  [N_0402]
R42  39 1%  [N_0402]
R43  39 1%  [N_0402]
R44  39 1%  [N_0402]
R45  39 1%  [N_0402]
R46  39 1%  [N_0402]
R47  39 1%  [N_0402]
R48  39 1%  [N_0402]
R49  39 1%  [N_0402]
R50  39 1%  [N_0402]
R51  39 1%  [N_0402]
R52  39 1%  [N_0402]
R53  39 1%  [N_0402]
R54  39 1%  [N_0402]
R55  39 1%  [N_0402]
R56  39 1%  [N_0402]
R57  39 1%  [N_0402]
R58  39 1%  [N_0402]
R59  39 1%  [N_0402]
R60  39 1%  [N_0402]
R61  39 1%  [N_0402]
R62  39 1%  [N_0402]
R63  39 1%  [N_0402]
R64  39 1%  [N_0402]
R65  39 1%  [N_0402]
R66  39 1%  [N_0402]
R67  39 1%  [N_0402]
R68  39 1%  [N_0402]
R69  39 1%  [N_0402]

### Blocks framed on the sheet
Source Termination 39 Ohms: R1 R5-R8 R10-R69

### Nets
A0: R10.2
DQ0: R38.2
E1: J8.28(E1)
E#: R1.2
EXT_VCCE_EN: J8.25(F2)
G#: R6.2
GND: J3.11(GND) J3.12(GND) J3.21(GND) J3.22(GND) J3.31(GND) J3.32(GND) J3.39(GND) J4.11(GND) J4.12(GND) J4.21(GND) J4.22(GND) J4.31(GND) J4.32(GND) J6.11(GND) J6.12(GND) J6.21(GND) J6.22(GND) J6.31(GND) J6.32(GND) J8.11(GND) J8.12(GND) J8.21(GND) J8.22(GND) J8.31(GND)
INT_VCCE_EN: J8.23(G2)
VCC_REG_EN: J8.27(E2)
VCCIO: J3.1(VCCIO0) J3.2(VCCIO0) J4.1(VCCIO1) J4.2(VCCIO1) J6.1(VCCIO2) J6.2(VCCIO2) J8.1(VCCIO5) J8.2(VCCIO3) J8.40(VCCIO4)
VCCIO_REG_EN: J8.29(D2)
VCCIO_VCCEXT_EN: J8.33(C1)
VDD_REG_EN: J8.35(B1)
VDD_SW_EN: J8.37(E3)
W#: R5.2
A0_1: J4.3(K12/A0) R10.1
A1: R11.2
A1_1: J4.5(M14/A1) R11.1
A2: R12.2
A2_1: J4.7(L14/A2) R12.1
A3: R13.2
A3_1: J4.9(M15/A3) R13.1
A4: R14.2
A4_1: J4.13(L15/A4) R14.1
A5: R15.2
A5_1: J4.15(K14/A5) R15.1
A6: R16.2
A6_1: J4.17(K15/A6) R16.1
A7: R17.2
A7_1: J4.19(H14/A7) R17.1
A8: R18.2
A8_1: J4.23(J16/A8) R18.1
A9: R19.2
A9_1: J4.25(H16/A9) R19.1
A10: R20.2
A10_1: J4.27(G16/A10) R20.1
A11: R21.2
A11_1: J4.29(F16/A11) R21.1
A12: R22.2
A12_1: J4.33(E16/A12) R22.1
A13: R23.2
A13_1: J4.35(D16/A13) R23.1
A14: R24.2
A14_1: J4.37(D14/A14) R24.1
A15: R25.2
A15_1: J4.39(G14/A15) R25.1
A16: R26.2
A16_1: J4.4(K13/A16) R26.1
A17: R27.2
A17_1: J4.6(N14/A17) R27.1
A18: R28.2
A18_1: J4.8(N16/A18) R28.1
A19: R29.2
A19_1: J4.10(M16/A19) R29.1
A20: R30.2
A20_1: J4.14(L16/A20) R30.1
A21: R31.2
A21_1: J4.16(K16/A21) R31.1
A22: R32.2
A22_1: J4.18(J14/A22) R32.1
A23: R33.2
A23_1: J4.20(J15/A23) R33.1
A24: R34.2
A24_1: J4.24(H15/A24) R34.1
A25: R35.2
A25_1: J4.26(G15/A25) R35.1
A26: R36.2
A26_1: J4.28(F15/A26) R36.1
A27: R37.2
A27_1: J4.30(E15/A27) R37.1
ADC_B: J8.34(G3)
ADC_CLK: J8.4(N3/ADC_CLK)
ADC_CN: J8.32(C2)
ADC_D0: J8.3(H6/ADC_D0)
ADC_D1: J8.5(M2/ADC_D1)
ADC_D2: J8.7(L2/ADC_D2)
ADC_D3: J8.9(L3/ADC_D3)
ADC_D4: J8.13(K4/ADC_D4)
ADC_D5: J8.15(K1/ADC_D5)
ADC_D6: J8.17(J3/ADC_D6)
ADC_D7: J8.19(H2/ADC_D7)
ADC_D8: J8.6(M1)
ADC_D9: J8.8(L1)
ADC_D10: J8.10(L5)
ADC_D11: J8.18(H3/TM)
CR#: R8.2
CR#_1: J3.34(B7/CR#) R8.1
DMON: J8.16(J2/DMON)
DQ0_1: J6.3(T12/DQ0) R38.1
DQ1: R39.2
DQ1_1: J6.5(R11/DQ1) R39.1
DQ2: R40.2
DQ2_1: J6.7(T11/DQ2) R40.1
DQ3: R41.2
DQ3_1: J6.9(P11/DQ3) R41.1
DQ4: R42.2
DQ4_1: J6.13(T10/DQ4) R42.1
DQ5: R43.2
DQ5_1: J6.15(R9/DQ5) R43.1
DQ6: R44.2
DQ6_1: J6.17(T9/DQ6) R44.1
DQ7: R45.2
DQ7_1: J6.19(P9/DQ7) R45.1
DQ8: R46.2
DQ8_1: J6.23(T8/DQ8) R46.1
DQ9: R47.2
DQ9_1: J6.25(P8/DQ9) R47.1
DQ10: R48.2
DQ10_1: J6.27(R7/DQ10) R48.1
DQ11: R49.2
DQ11_1: J6.29(P7/DQ11) R49.1
DQ12: R50.2
DQ12_1: J6.33(L7/DQ12) R50.1
DQ13: R51.2
DQ13_1: J6.35(N6/DQ13) R51.1
DQ14: R52.2
DQ14_1: J6.37(R4/DQ14) R52.1
DQ15: R53.2
DQ15_1: J6.39(T3/DQ15) R53.1
DQ16: R54.2
DQ16_1: J6.4(T14/DQ16) R54.1
DQ17: R55.2
DQ17_1: J6.6(R13/DQ17) R55.1
DQ18: R56.2
DQ18_1: J6.8(M11/DQ18) R56.1
DQ19: R57.2
DQ19_1: J6.10(N10/DQ19) R57.1
DQ20: R58.2
DQ20_1: J6.14(P10/DQ20) R58.1
DQ21: R59.2
DQ21_1: J6.16(R10/DQ21) R59.1
DQ22: R60.2
DQ22_1: J6.18(N9/DQ22) R60.1
DQ23: R61.2
DQ23_1: J6.20(M8/DQ23) R61.1
DQ24: R62.2
DQ24_1: J6.24(L8/DQ24) R62.1
DQ25: R63.2
DQ25_1: J6.26(M6/DQ25) R63.1
DQ26: R64.2
DQ26_1: J6.28(R8/DQ26) R64.1
DQ27: R65.2
DQ27_1: J6.30(T7/DQ27) R65.1
DQ28: R66.2
DQ28_1: J6.34(R6/DQ28) R66.1
DQ29: R67.2
DQ29_1: J6.36(T5/DQ29) R67.1
DQ30: R68.2
DQ30_1: J6.38(P4/DQ30) R68.1
DQ31: R69.2
DQ31_1: J6.40(T4/DQ31) R69.1
E#_1: J4.34(E14/E#) R1.1
G#_1: J4.38(F14/G#) R6.1
INT#: J8.14(J1/INT#)
PG#: R7.2
PG#_1: J4.40(B16/PG#) R7.1
TID_CLK: J3.37(B4/TID_CLK)
TID_IN: J3.35(B5/TID_IN)
TM: J8.24(G1)
TM_CLK: J3.33(B6/TM_CLK)
W#_1: J4.36(C15/W#) R5.1

Not connected (* = marked no-connect by the designer): J3 3(A13) 4(C13) 5(F8) 6(B12) 7(C12) 8(E11) 9(E10) 10(D10) 13(F9) 14(C10) 15(E8) 16(E9) 17(E7) 18(D8) 19(D7) 20(C7) 23(C5/A28) 24(D6) 25(E6/A29) 26(C4) 27(A10/A30) 28(F7) 29(D9/A31) 30(B9) 36(A5) 38(A4) 40(A3); J8 20(H1)* 26(F1)* 30(D1)* 36(D3)* 38(F3)* 39(F5)

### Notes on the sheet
- 142-Ball FBGA Connection to Lattice MACHO3 Development Kit
- PAGE2
- FROM CONNECTOR
- TO BGA
- (near R26) FROM CONNECTOR
- DATE:
- TITLE:
- Lat_Parallel_142BGA_V2
- DESIGNED BY:
- CHECK BY:
- AVAL
- CUSTOMER:
- CUST. P/N:
- BGA-142
- CUST. CONTACT:
- JOB#
- QDS10232_AVL
- APPROVE BY:
- SCALE: NONE
- AVALANCHE
- SIZE : B
- REV 0.4
- SHEET:  4 OF 4

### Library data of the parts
R1 R5 R7 R10-R30 R32-R38 R40 R41 R43-R56 R58-R69 = R-US_R0603: RES 39 OHM 1% 1/16W 0402; Part Number: RC0402FR-0739RL
R6 R8 R42 R57 = R-US_R0603: RES 39 OHM 1% 1/16W 0402; Part Number: RC0402FR-0739RL; Value: 25
R31 R39 = R-US_R0603: RES 39 OHM 1% 1/16W 0402; Part Number: RC0402FR-0739RL; Value: 12

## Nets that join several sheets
A0: PAGE01_BGA (U1.M9), PAGE02_CIRCUIT (A0.1), PAGE04_CON_J3-J4-J6-J8 (R10.2)
AMON: PAGE01_BGA (U1.H2), PAGE02_CIRCUIT (J1.1)
C_SENSE: PAGE02_CIRCUIT (J1.4), PAGE03_USB_REG (U13.9)
DQ0: PAGE01_BGA (U1.C3), PAGE02_CIRCUIT (DQ0.1 R70.2), PAGE04_CON_J3-J4-J6-J8 (R38.2)
E1: PAGE02_CIRCUIT (U15.5), PAGE04_CON_J3-J4-J6-J8 (J8.28)
E#: PAGE01_BGA (U1.P8), PAGE02_CIRCUIT (E#.1), PAGE04_CON_J3-J4-J6-J8 (R1.2)
EXT_VCCE_EN: PAGE02_CIRCUIT (U6.3), PAGE04_CON_J3-J4-J6-J8 (J8.25)
G#: PAGE01_BGA (U1.P7), PAGE02_CIRCUIT (G#.1), PAGE04_CON_J3-J4-J6-J8 (R6.2)
GND: PAGE01_BGA (66 pins), PAGE02_CIRCUIT (65 pins), PAGE03_USB_REG (37 pins), PAGE04_CON_J3-J4-J6-J8 (24 pins)
INT_VCCE_EN: PAGE02_CIRCUIT (U5.3), PAGE04_CON_J3-J4-J6-J8 (J8.23)
RESMIO: PAGE01_BGA (U1.H3), PAGE02_CIRCUIT (J1.2)
VCC: PAGE01_BGA (41 pins), PAGE03_USB_REG (5 pins)
VCC_M: PAGE02_CIRCUIT (28 pins), PAGE03_USB_REG (7 pins)
VCC_REG: PAGE02_CIRCUIT (C20.1 C21.1 L3.1), PAGE03_USB_REG (7 pins)
VCC_REG_EN: PAGE02_CIRCUIT (U7.3), PAGE04_CON_J3-J4-J6-J8 (J8.27)
VCCEXT: PAGE02_CIRCUIT (6 pins), PAGE03_USB_REG (J12.3)
VCCIO: PAGE02_CIRCUIT (C13.1 C14.1 J2.1 L1.1), PAGE03_USB_REG (7 pins), PAGE04_CON_J3-J4-J6-J8 (9 pins)
VCCIO_REG_EN: PAGE03_USB_REG (U14.3), PAGE04_CON_J3-J4-J6-J8 (J8.29)
VCCIO_VCCEXT_EN: PAGE03_USB_REG (U10.3), PAGE04_CON_J3-J4-J6-J8 (J8.33)
VCCQ: PAGE01_BGA (25 pins), PAGE02_CIRCUIT (VCCQ.1), PAGE03_USB_REG (8 pins)
VDD: PAGE01_BGA (C51.1 U1.K12), PAGE02_CIRCUIT (7 pins), PAGE03_USB_REG (J14.2)
VDD_REG_EN: PAGE03_USB_REG (U16.3), PAGE04_CON_J3-J4-J6-J8 (J8.35)
VDD_SW_EN: PAGE03_USB_REG (U17.3), PAGE04_CON_J3-J4-J6-J8 (J8.37)
VPPW: PAGE01_BGA (C52.1 U1.J13), PAGE02_CIRCUIT (7 pins)
VWR: PAGE01_BGA (C53.1 U1.H12), PAGE02_CIRCUIT (7 pins)
W#: PAGE01_BGA (U1.M8), PAGE02_CIRCUIT (W#.1), PAGE04_CON_J3-J4-J6-J8 (R5.2)
A1: PAGE01_BGA (U1.N9), PAGE04_CON_J3-J4-J6-J8 (R11.2)
A2: PAGE01_BGA (U1.N2), PAGE04_CON_J3-J4-J6-J8 (R12.2)
A3: PAGE01_BGA (U1.M4), PAGE04_CON_J3-J4-J6-J8 (R13.2)
A4: PAGE01_BGA (U1.N4), PAGE04_CON_J3-J4-J6-J8 (R14.2)
A5: PAGE01_BGA (U1.N5), PAGE04_CON_J3-J4-J6-J8 (R15.2)
A6: PAGE01_BGA (U1.P3), PAGE04_CON_J3-J4-J6-J8 (R16.2)
A7: PAGE01_BGA (U1.P5), PAGE04_CON_J3-J4-J6-J8 (R17.2)
A8: PAGE01_BGA (U1.M11), PAGE04_CON_J3-J4-J6-J8 (R18.2)
A9: PAGE01_BGA (U1.L11), PAGE04_CON_J3-J4-J6-J8 (R19.2)
A10: PAGE01_BGA (U1.N13), PAGE04_CON_J3-J4-J6-J8 (R20.2)
A11: PAGE01_BGA (U1.M12), PAGE04_CON_J3-J4-J6-J8 (R21.2)
A12: PAGE01_BGA (U1.N10), PAGE04_CON_J3-J4-J6-J8 (R22.2)
A13: PAGE01_BGA (U1.P10), PAGE04_CON_J3-J4-J6-J8 (R23.2)
A14: PAGE01_BGA (U1.M13), PAGE04_CON_J3-J4-J6-J8 (R24.2)
A15: PAGE01_BGA (U1.L13), PAGE04_CON_J3-J4-J6-J8 (R25.2)
A16: PAGE01_BGA (U1.P6), PAGE04_CON_J3-J4-J6-J8 (R26.2)
A17: PAGE01_BGA (U1.N6), PAGE04_CON_J3-J4-J6-J8 (R27.2)
A18: PAGE01_BGA (U1.N11), PAGE04_CON_J3-J4-J6-J8 (R28.2)
A19: PAGE01_BGA (U1.L12), PAGE04_CON_J3-J4-J6-J8 (R29.2)
A20: PAGE01_BGA (U1.P12), PAGE04_CON_J3-J4-J6-J8 (R30.2)
A21: PAGE01_BGA (U1.M7), PAGE04_CON_J3-J4-J6-J8 (R31.2)
A22: PAGE01_BGA (U1.L3), PAGE04_CON_J3-J4-J6-J8 (R32.2)
A23: PAGE01_BGA (U1.M3), PAGE04_CON_J3-J4-J6-J8 (R33.2)
A24: PAGE01_BGA (U1.K13), PAGE04_CON_J3-J4-J6-J8 (R34.2)
A25: PAGE01_BGA (U1.L4), PAGE04_CON_J3-J4-J6-J8 (R35.2)
A26: PAGE01_BGA (U1.M2), PAGE04_CON_J3-J4-J6-J8 (R36.2)
ADC_B: PAGE02_CIRCUIT (U8.12), PAGE04_CON_J3-J4-J6-J8 (J8.34)
ADC_CLK: PAGE02_CIRCUIT (U8.11), PAGE04_CON_J3-J4-J6-J8 (J8.4)
ADC_CN: PAGE02_CIRCUIT (U8.10), PAGE04_CON_J3-J4-J6-J8 (J8.32)
ADC_D0: PAGE02_CIRCUIT (U8.13), PAGE04_CON_J3-J4-J6-J8 (J8.3)
ADC_D1: PAGE02_CIRCUIT (U8.14), PAGE04_CON_J3-J4-J6-J8 (J8.5)
ADC_D2: PAGE02_CIRCUIT (U8.15), PAGE04_CON_J3-J4-J6-J8 (J8.7)
ADC_D3: PAGE02_CIRCUIT (U8.16), PAGE04_CON_J3-J4-J6-J8 (J8.9)
ADC_D4: PAGE02_CIRCUIT (U8.17), PAGE04_CON_J3-J4-J6-J8 (J8.13)
ADC_D5: PAGE02_CIRCUIT (U8.18), PAGE04_CON_J3-J4-J6-J8 (J8.15)
ADC_D6: PAGE02_CIRCUIT (U8.22), PAGE04_CON_J3-J4-J6-J8 (J8.17)
ADC_D7: PAGE02_CIRCUIT (U8.23), PAGE04_CON_J3-J4-J6-J8 (J8.19)
ADC_D8: PAGE02_CIRCUIT (U8.24), PAGE04_CON_J3-J4-J6-J8 (J8.6)
ADC_D9: PAGE02_CIRCUIT (U8.1), PAGE04_CON_J3-J4-J6-J8 (J8.8)
ADC_D10: PAGE02_CIRCUIT (U8.2), PAGE04_CON_J3-J4-J6-J8 (J8.10)
ADC_D11: PAGE02_CIRCUIT (U8.3), PAGE04_CON_J3-J4-J6-J8 (J8.18)
CR#: PAGE01_BGA (U1.J2), PAGE04_CON_J3-J4-J6-J8 (R8.2)
DMON: PAGE01_BGA (U1.G2), PAGE04_CON_J3-J4-J6-J8 (J8.16)
DQ1: PAGE01_BGA (U1.D5), PAGE04_CON_J3-J4-J6-J8 (R39.2)
DQ2: PAGE01_BGA (U1.C5), PAGE04_CON_J3-J4-J6-J8 (R40.2)
DQ3: PAGE01_BGA (U1.E7), PAGE04_CON_J3-J4-J6-J8 (R41.2)
DQ4: PAGE01_BGA (U1.D9), PAGE04_CON_J3-J4-J6-J8 (R42.2)
DQ5: PAGE01_BGA (U1.D11), PAGE04_CON_J3-J4-J6-J8 (R43.2)
DQ6: PAGE01_BGA (U1.C12), PAGE04_CON_J3-J4-J6-J8 (R44.2)
DQ7: PAGE01_BGA (U1.G12), PAGE04_CON_J3-J4-J6-J8 (R45.2)
DQ8: PAGE01_BGA (U1.D4), PAGE04_CON_J3-J4-J6-J8 (R46.2)
DQ9: PAGE01_BGA (U1.D6), PAGE04_CON_J3-J4-J6-J8 (R47.2)
DQ10: PAGE01_BGA (U1.C6), PAGE04_CON_J3-J4-J6-J8 (R48.2)
DQ11: PAGE01_BGA (U1.C8), PAGE04_CON_J3-J4-J6-J8 (R49.2)
DQ12: PAGE01_BGA (U1.F9), PAGE04_CON_J3-J4-J6-J8 (R50.2)
DQ13: PAGE01_BGA (U1.E10), PAGE04_CON_J3-J4-J6-J8 (R51.2)
DQ14: PAGE01_BGA (U1.G11), PAGE04_CON_J3-J4-J6-J8 (R52.2)
DQ15: PAGE01_BGA (U1.E13), PAGE04_CON_J3-J4-J6-J8 (R53.2)
DQ16: PAGE01_BGA (U1.E5), PAGE04_CON_J3-J4-J6-J8 (R54.2)
DQ17: PAGE01_BGA (U1.F6), PAGE04_CON_J3-J4-J6-J8 (R55.2)
DQ18: PAGE01_BGA (U1.E8), PAGE04_CON_J3-J4-J6-J8 (R56.2)
DQ19: PAGE01_BGA (U1.C10), PAGE04_CON_J3-J4-J6-J8 (R57.2)
DQ20: PAGE01_BGA (U1.D13), PAGE04_CON_J3-J4-J6-J8 (R58.2)
DQ21: PAGE01_BGA (U1.F13), PAGE04_CON_J3-J4-J6-J8 (R59.2)
DQ22: PAGE01_BGA (U1.G3), PAGE04_CON_J3-J4-J6-J8 (R60.2)
DQ23: PAGE01_BGA (U1.G4), PAGE04_CON_J3-J4-J6-J8 (R61.2)
DQ24: PAGE01_BGA (U1.C7), PAGE04_CON_J3-J4-J6-J8 (R62.2)
DQ25: PAGE01_BGA (U1.C9), PAGE04_CON_J3-J4-J6-J8 (R63.2)
DQ26: PAGE01_BGA (U1.D10), PAGE04_CON_J3-J4-J6-J8 (R64.2)
DQ27: PAGE01_BGA (U1.E12), PAGE04_CON_J3-J4-J6-J8 (R65.2)
DQ28: PAGE01_BGA (U1.E3), PAGE04_CON_J3-J4-J6-J8 (R66.2)
DQ29: PAGE01_BGA (U1.D2), PAGE04_CON_J3-J4-J6-J8 (R67.2)
DQ30: PAGE01_BGA (U1.F2), PAGE04_CON_J3-J4-J6-J8 (R68.2)
DQ31: PAGE01_BGA (U1.E2), PAGE04_CON_J3-J4-J6-J8 (R69.2)
INT#: PAGE01_BGA (U1.G13), PAGE04_CON_J3-J4-J6-J8 (J8.14)
PG#: PAGE01_BGA (U1.K3), PAGE04_CON_J3-J4-J6-J8 (R7.2)
TID_CLK: PAGE01_BGA (U1.K2), PAGE04_CON_J3-J4-J6-J8 (J3.37)
TID_IN: PAGE01_BGA (U1.L2), PAGE04_CON_J3-J4-J6-J8 (J3.35)
TM: PAGE01_BGA (U1.H13), PAGE04_CON_J3-J4-J6-J8 (J8.24)
TM_CLK: PAGE01_BGA (U1.M6), PAGE04_CON_J3-J4-J6-J8 (J3.33)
